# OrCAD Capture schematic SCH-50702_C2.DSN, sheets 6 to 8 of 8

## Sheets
6 06. MCU Link: size C
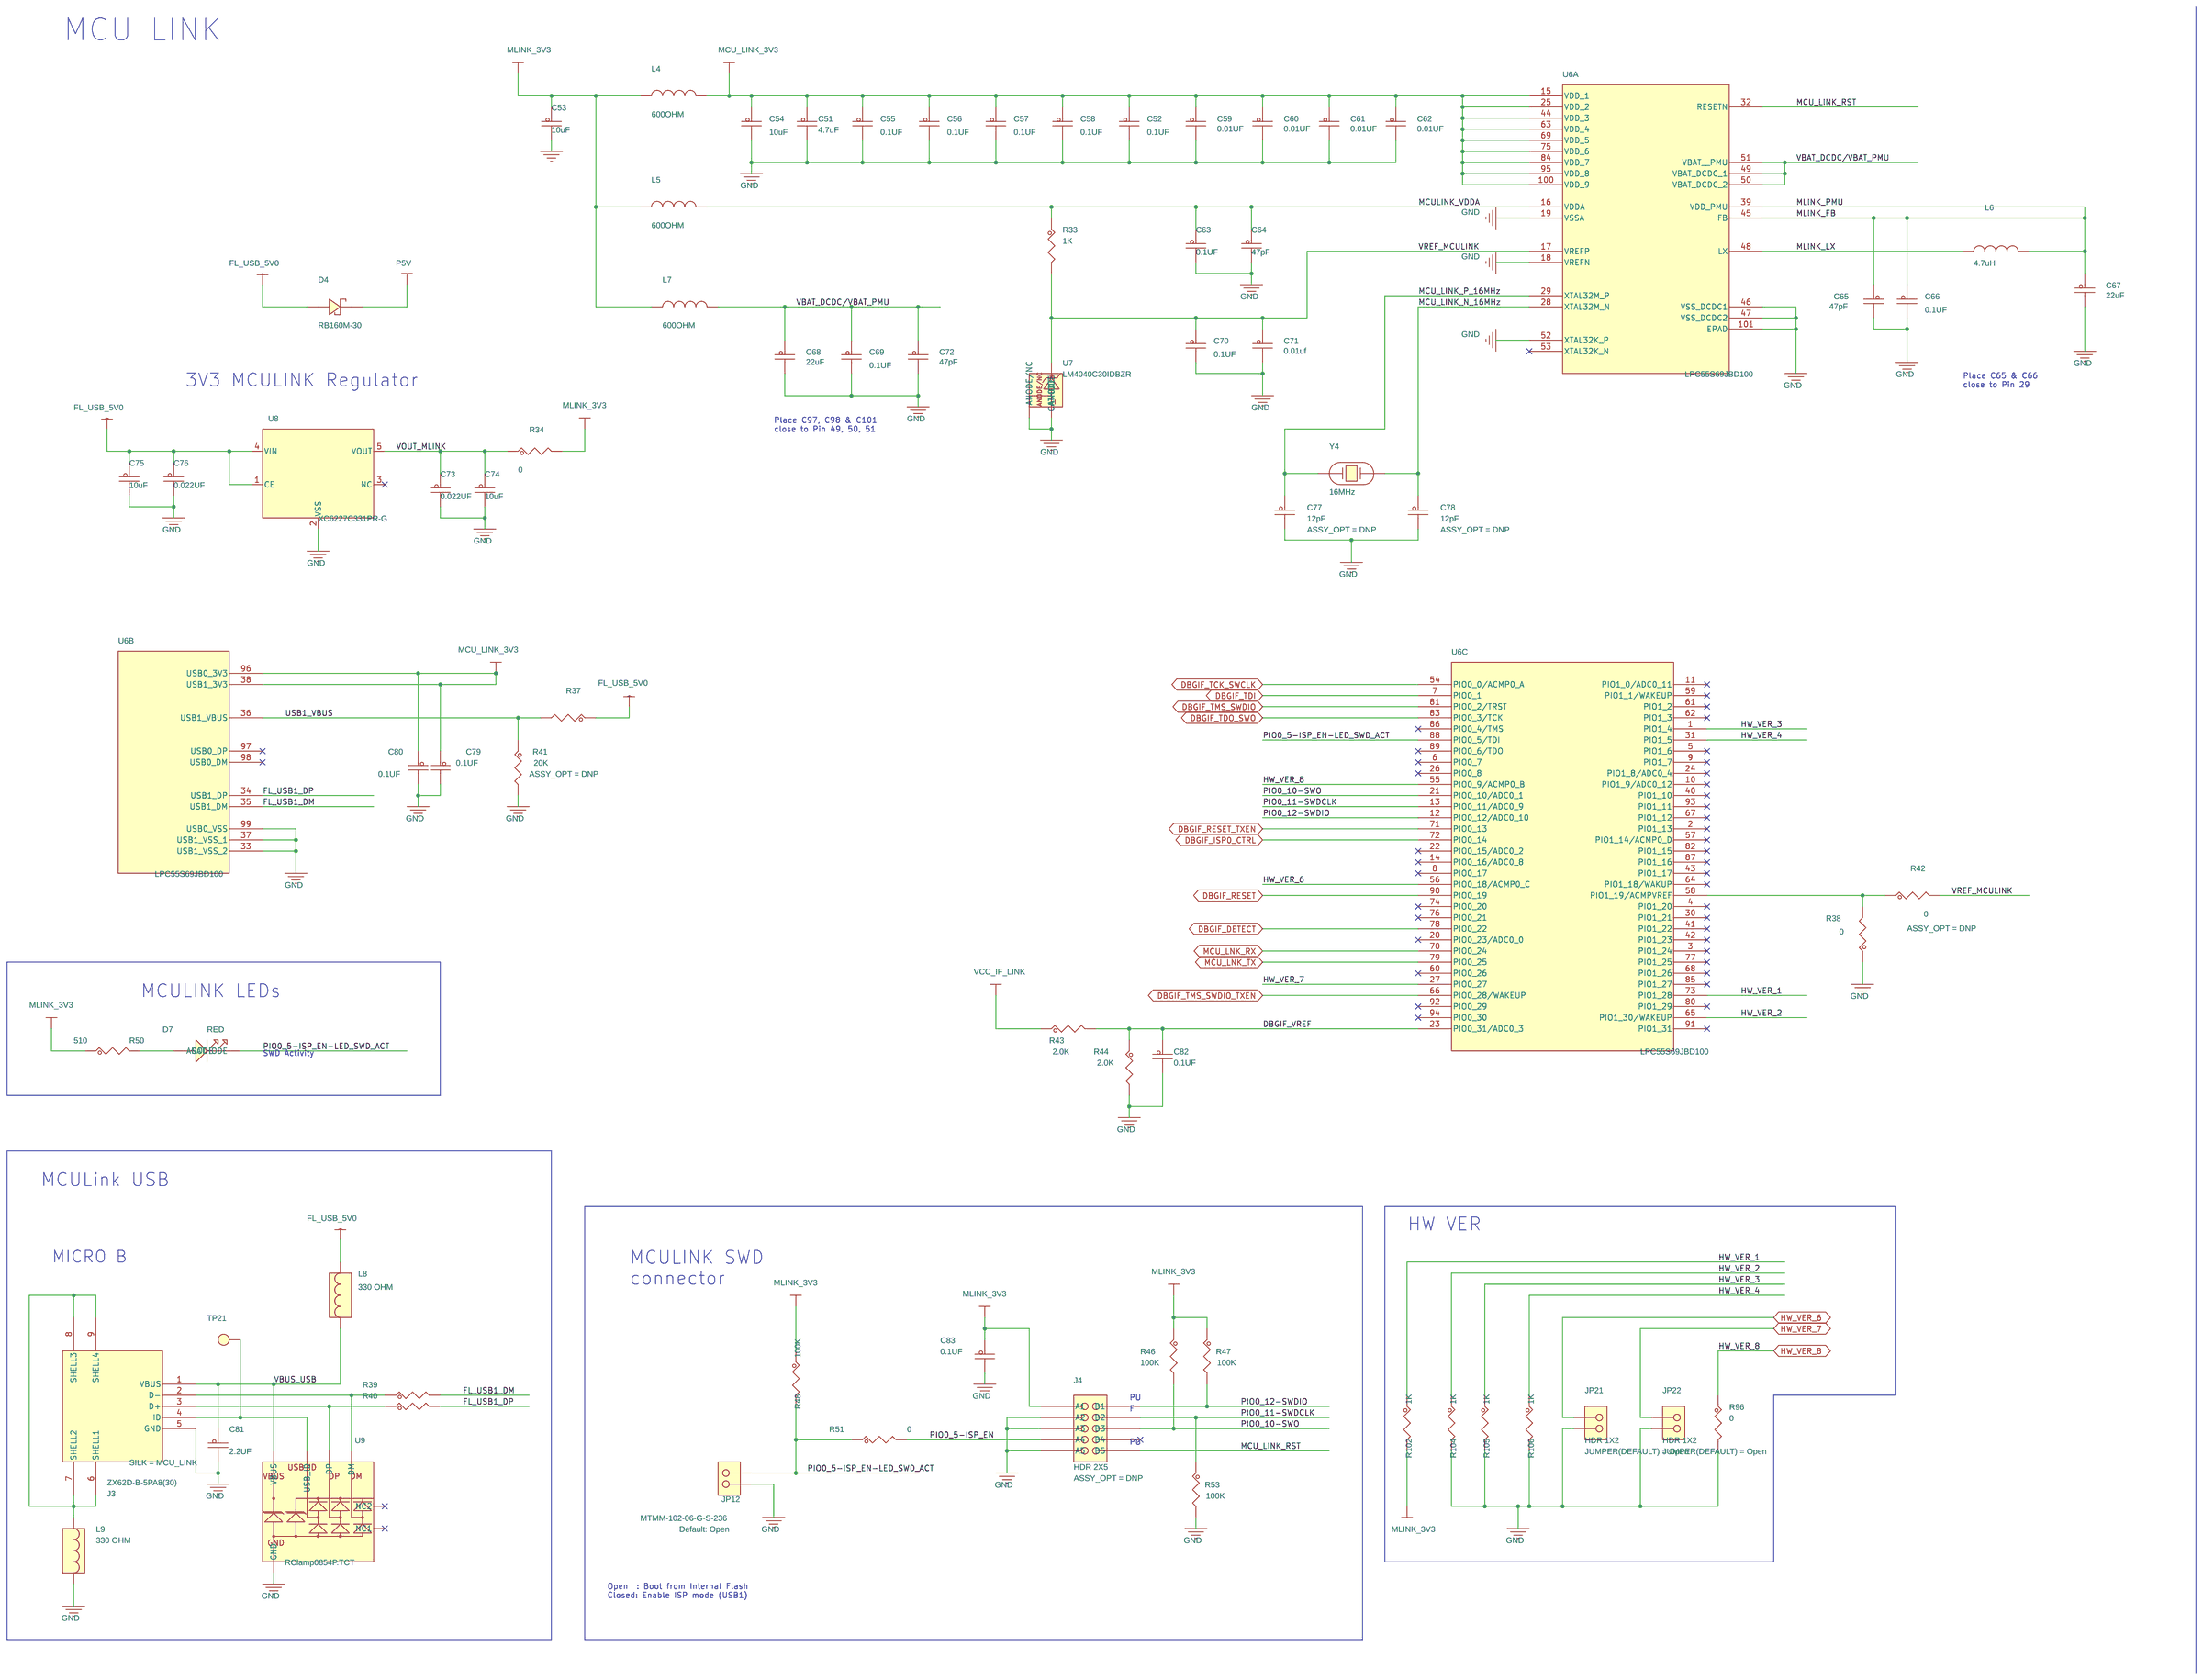
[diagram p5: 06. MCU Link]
7 07. MCU Link SWD: size C
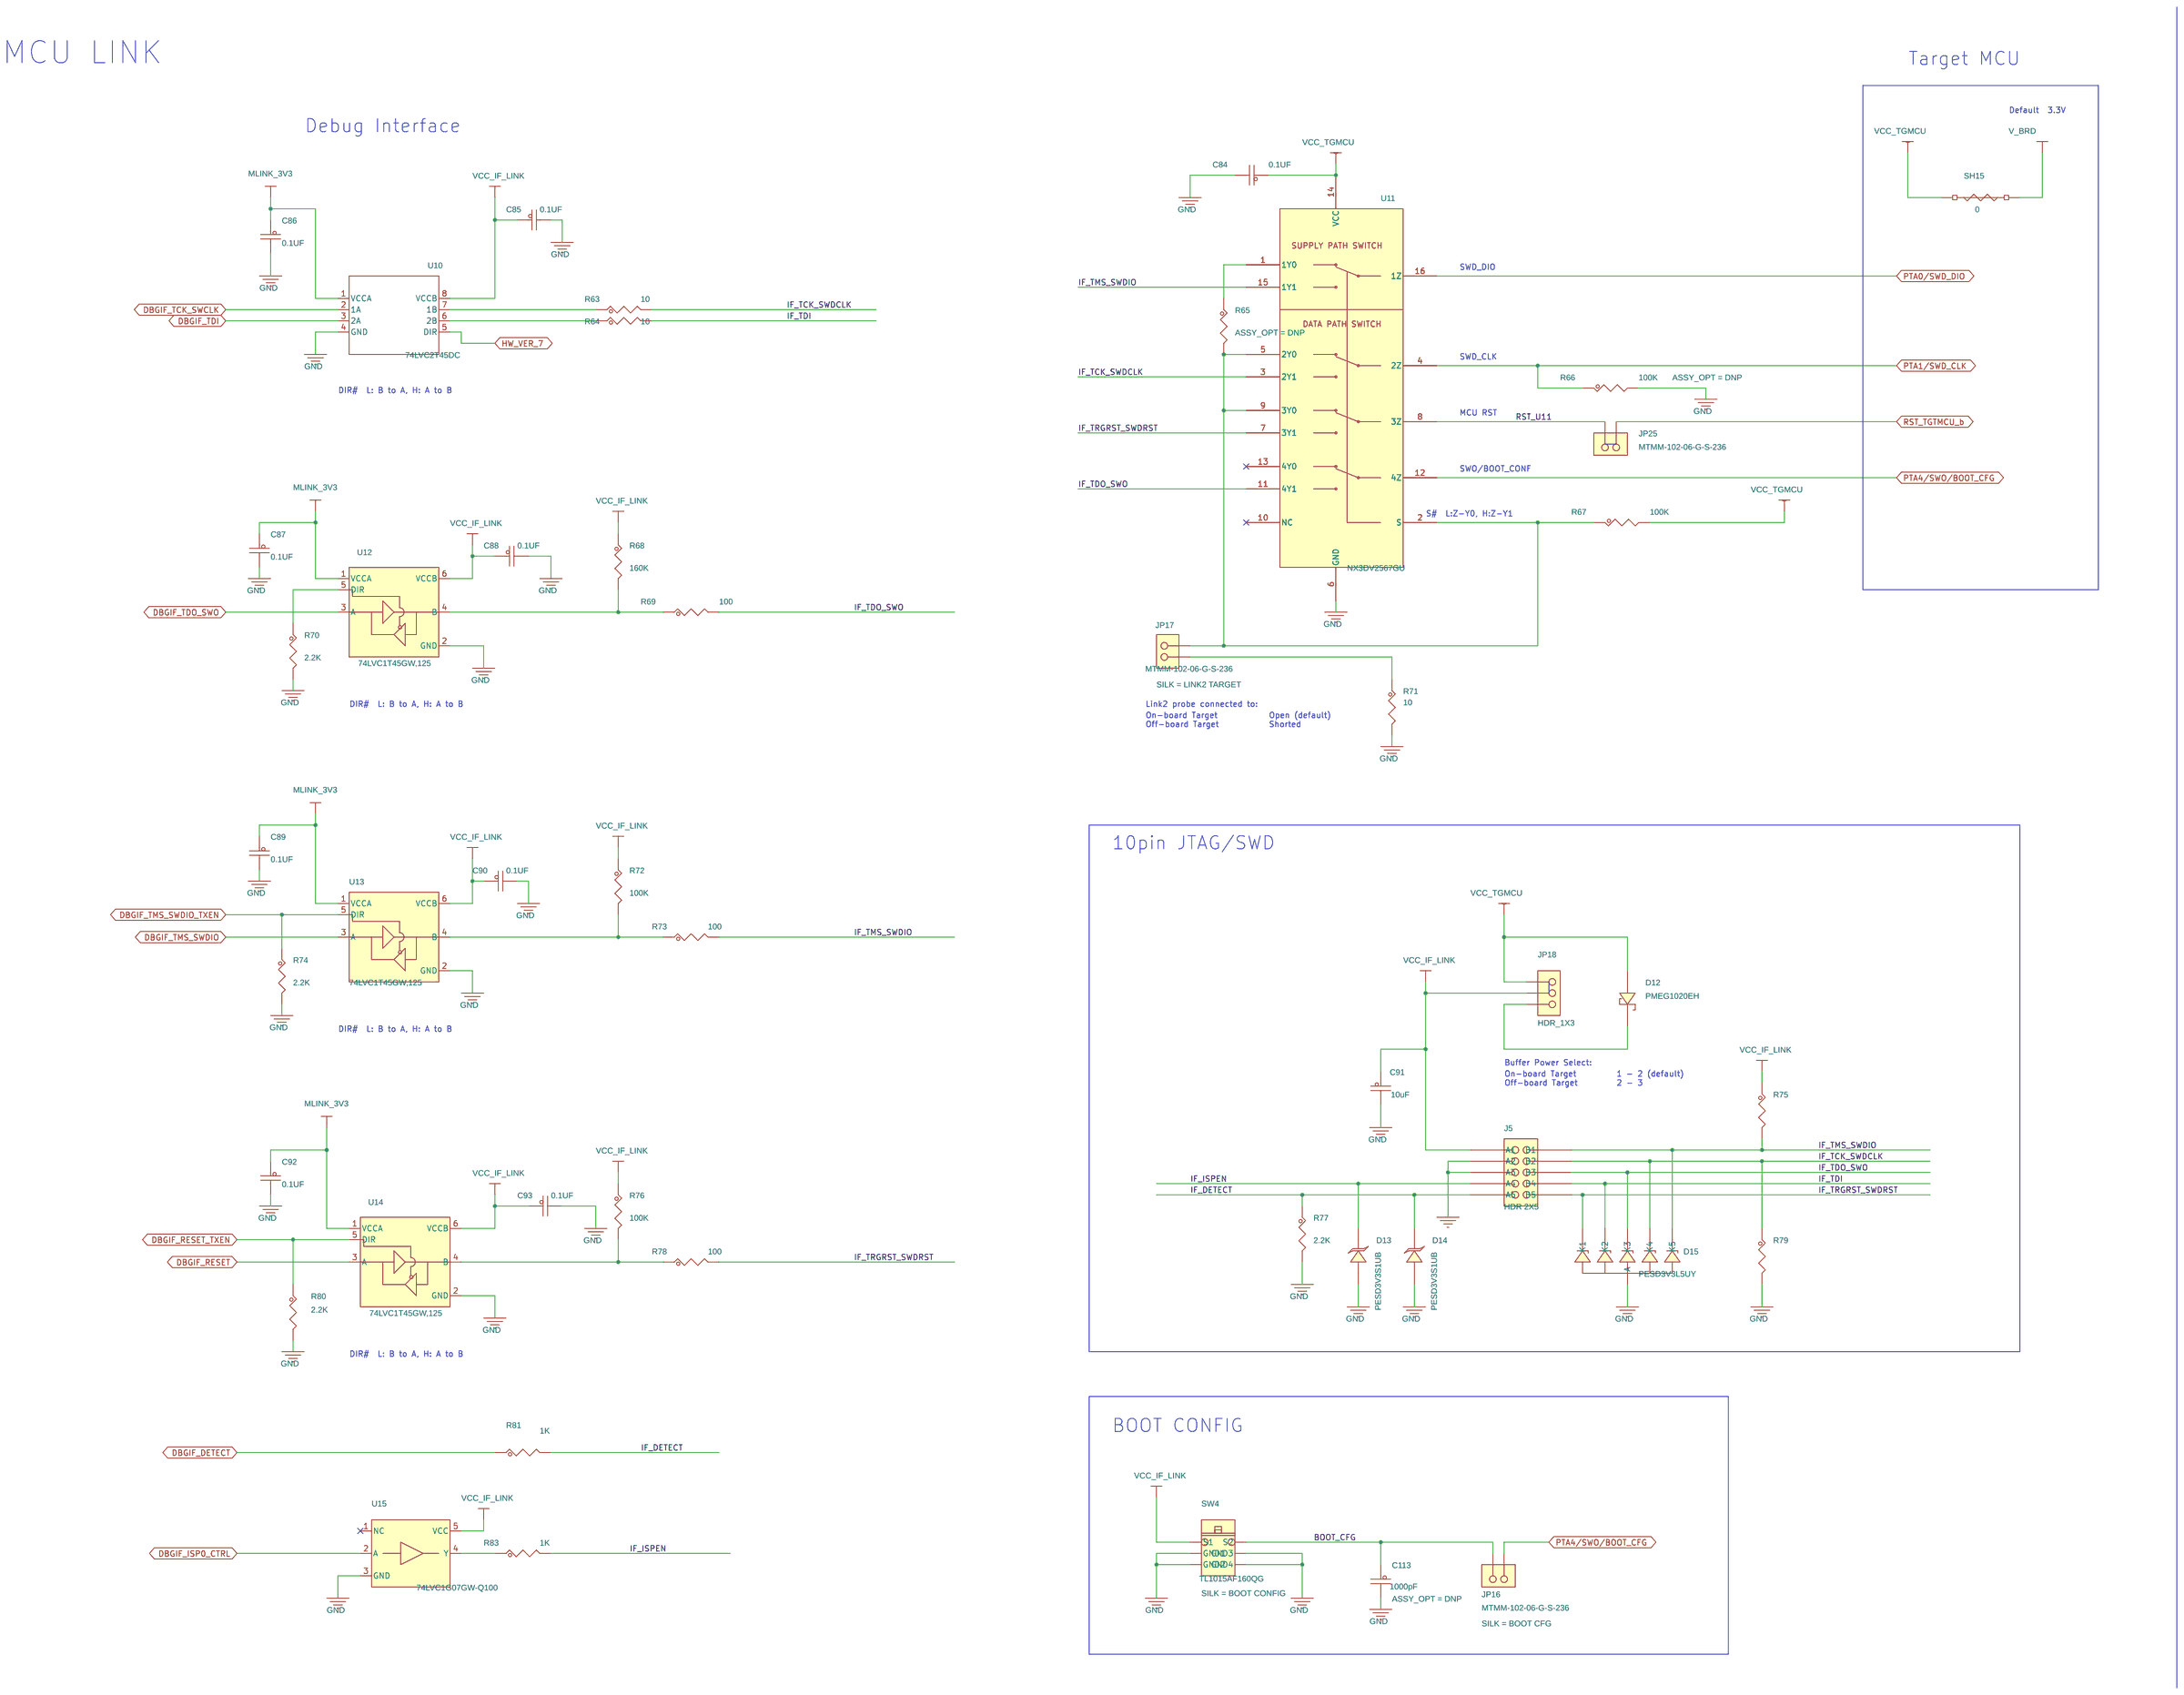
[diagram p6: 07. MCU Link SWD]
8 08. MCU Link IO: size C
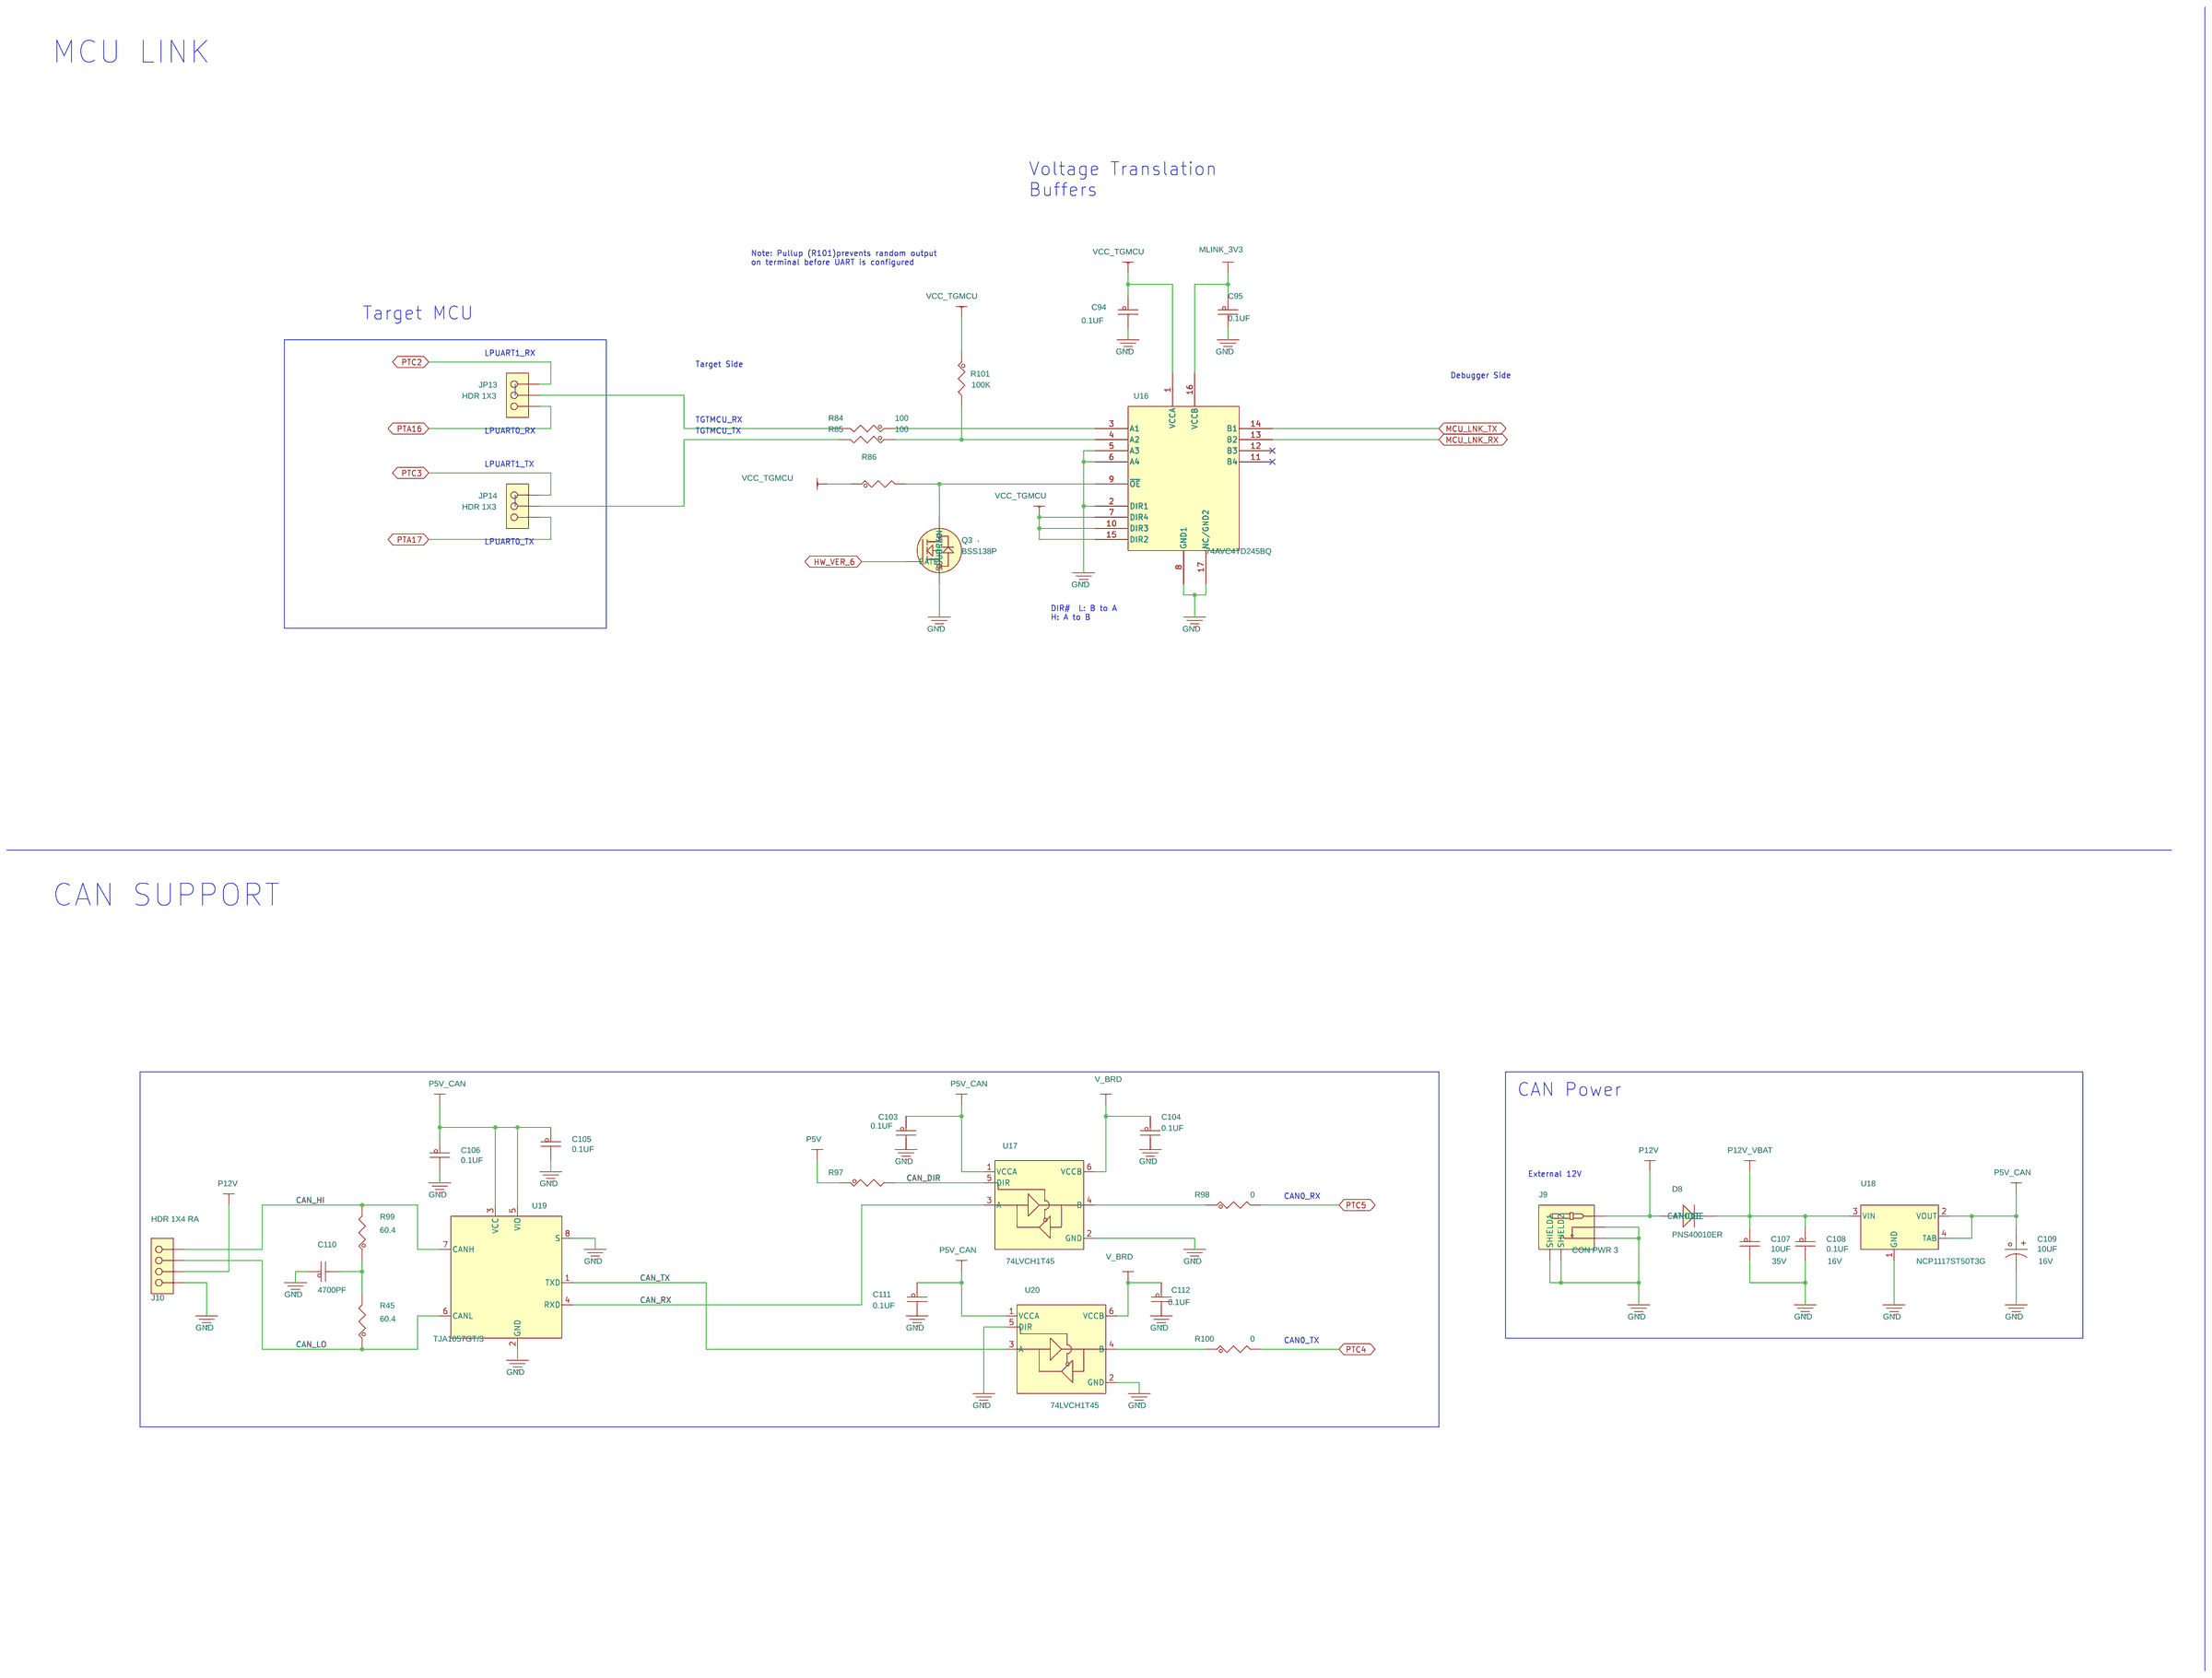
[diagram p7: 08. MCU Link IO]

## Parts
sheet 06. MCU Link
C51  4.7uF  [CC0603_OV]
C52  0.1UF  [CC0402_25]
C53  10uF  [CC0805_OV]
C54  10uF  [CC0805_OV]
C55  0.1UF  [CC0402_25]
C56  0.1UF  [CC0402_25]
C57  0.1UF  [CC0402_25]
C58  0.1UF  [CC0402_25]
C59  0.01UF  [CC0402_25]
C60  0.01UF  [CC0402_25]
C61  0.01UF  [CC0402_25]
C62  0.01UF  [CC0402_25]
C63  0.1UF  [CC0402_25]
C64  47pF  [CC0603_OV]
C65  47pF  [CC0603_OV]
C66  0.1UF  [CC0402_25]
C67  22uF  [CC0603_OV]
C68  22uF  [CC0603_OV]
C69  0.1UF  [CC0402_25]
C70  0.1UF  [CC0402_25]
C71  0.01uf  [CC0603_OV]
C72  47pF  [CC0603_OV]
C73  0.022UF  [CC0603_OV]
C74  10uF  [CC0805_OV]
C75  10uF  [CC0805_OV]
C76  0.022UF  [CC0603_OV]
C77  12pF  [CC0402_25]
C78  12pF  [CC0402_25]
C79  0.1UF  [CC0402_25]
C80  0.1UF  [CC0402_25]
C81  2.2UF  [CC0402_25]
C82  0.1UF  [CC0402_25]
C83  0.1UF  [CC0402_25]
D4  RB160M-30  [pmdu_sod123]
D7  RED  [LED_0603]
J3  ZX62D-B-5PA8(30)  [con9_microB_usb_shell_th]
J4  HDR 2X5  [hdr205_50_th]
JP12  MTMM-102-06-G-S-236  [hdr102_tmm]
JP21  HDR 1X2  [hdr102_338h]
JP22  HDR 1X2  [hdr102_338h]
L4  600OHM  [ind_1p8x1mm_sm]
L5  600OHM  [ind_1p8x1mm_sm]
L6  4.7uH  [ind_5p2x5p2]
L7  600OHM  [ind_1p8x1mm_sm]
L8  330 OHM  [ind_1608]
L9  330 OHM  [ind_1608]
R33  1K  [RC0402_25]
R34  0  [RC0603_OV]
R37  10K  [RC0603_OV]
R38  0  [RC0603_OV]
R39  0  [RC0402_25]
R40  0  [RC0402_25]
R41  20K  [RC0402_25]
R42  0  [RC0603_OV]
R43  2.0K  [RC0603_OV]
R44  2.0K  [RC0603_OV]
R46  100K  [RC0402_25]
R47  100K  [RC0402_25]
R48  100K  [RC0402_25]
R50  510  [RC0402_25]
R51  0  [RC0603_OV]
R53  100K  [RC0402_25]
R96  0  [RC0603_OV]
R102  1K  [RC0402_25]
R104  1K  [RC0402_25]
R105  1K  [RC0402_25]
R106  1K  [RC0402_25]
TP21  TP_35MIL  [testpoint_35mil]
U6  LPC55S69JBD100  [hlqfp100_0p5_14x14]  (sections A,B,C)
U7  LM4040C30IDBZR  [SOT23-3]
U8  XC6227C331PR-G  [SOT89-5]
U9  RClamp0854P.TCT  [slp1616p6]
Y4  16MHz  [xtal2_3p3x2p6]
sheet 07. MCU Link SWD
C84  0.1UF  [CC0402_25]
C85  0.1UF  [CC0402_25]
C86  0.1UF  [CC0402_25]
C87  0.1UF  [CC0402_25]
C88  0.1UF  [CC0402_25]
C89  0.1UF  [CC0402_25]
C90  0.1UF  [CC0402_25]
C91  10uF  [cc0402_tol0p2]
C92  0.1UF  [CC0402_25]
C93  0.1UF  [CC0402_25]
C113  1000pF  [CC0402_25]
D12  PMEG1020EH  [SOD123LF]
D13  PESD3V3S1UB  [sod523]
D14  PESD3V3S1UB  [sod523]
D15  PESD3V3L5UY  [sot-363_0p65_smt]
J5  HDR 2X5  [hdr205_50_th]
JP16  MTMM-102-06-G-S-236  [hdr102_tmm]
JP17  MTMM-102-06-G-S-236  [hdr102_tmm]
JP18  HDR_1X3  [hdr103_78mil]
JP25  MTMM-102-06-G-S-236  [hdr102_tmm]
R63  10  [RC0402_25]
R64  10  [RC0402_25]
R65  0  [RC0402_25]
R66  100K  [RC0402_25]
R67  100K  [RC0402_25]
R68  160K  [RC0402_25]
R69  100  [RC0402_25]
R70  2.2K  [RC0402_25]
R71  10  [RC0402_25]
R72  100K  [RC0402_25]
R73  100  [RC0402_25]
R74  2.2K  [RC0402_25]
R75  10K  [RC0402_25]
R76  100K  [RC0402_25]
R77  2.2K  [RC0402_25]
R78  100  [RC0402_25]
R79  10K  [RC0402_25]
R80  2.2K  [RC0402_25]
R81  1K  [RC0402_25]
R83  1K  [RC0402_25]
SH15  0  [SH0402]
SW4  TL1015AF160QG  [sw2_spst_4x3_sm]
U10  74LVC2T45DC  [SSOP8_DCU]
U11  NX3DV2567GU  [pqfn16_0p4_2p65x1p85]
U12  74LVC1T45GW,125  [SOT-363_0P65_SMT]
U13  74LVC1T45GW,125  [SOT-363_0P65_SMT]
U14  74LVC1T45GW,125  [SOT-363_0P65_SMT]
U15  74LVC1G07GW-Q100  [sc70-5]
sheet 08. MCU Link IO
C94  0.1UF  [CC0402_25]
C95  0.1UF  [CC0402_25]
C103  0.1UF  [CC0402_25]
C104  0.1UF  [CC0402_25]
C105  0.1UF  [CC0402_25]
C106  0.1UF  [CC0402_25]
C107  10UF  [CC0603_OV]
C108  0.1UF  [CC0402_25]
C109  10UF  [CC3216]
C110  4700PF  [CC0603_OV]
C111  0.1UF  [CC0402_25]
C112  0.1UF  [CC0402_25]
D8  PNS40010ER  [sod123w]
J9  CON PWR 3  [con3_pwr_jack_th_pj051a]
J10  HDR 1X4 RA  [con_hdr_4m_100_th_ra]
JP13  HDR 1X3  [CONN_HDR_3X1]
JP14  HDR 1X3  [CONN_HDR_3X1]
Q3  BSS138P  [sot23_a]
R45  60.4  [RC0805_OV]
R84  100  [RC0402_25]
R85  100  [RC0402_25]
R86  10K  [RC0402_25]
R97  4.7K  [RC0402_25]
R98  0  [RC0402_25]
R99  60.4  [RC0805_OV]
R100  0  [RC0402_25]
R101  100K  [RC0402_25]
U16  74AVC4TD245BQ  [dhvqfn16_0p5_3p6x2p6]
U17  74LVCH1T45  [udfn6_1x1p5mm]
U18  NCP1117ST50T3G  [sot223]
U19  TJA1057GT/3  [SO8_1P27_4X5]
U20  74LVCH1T45  [udfn6_1x1p5mm]

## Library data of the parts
C51 = CAP_NP: CAP CER 4.7uF 25V 10% X6S AEC-Q200 0603; AGILE_PN: 150-79698; CAD_APPROVED: Yes; FPLIST: CC0603_OV,CC0603; HEIGHT: 1MM; MFG_NAME01: MURATA; MFG_PN01: GRT188C81E475KE13; Package Size: 0603; ROHS: Yes; Rated Voltage: 25V; Temp Range: -55C to +105C; Tolerance: 10%; VOLTAGE: 25V
C52 C55-C58 C63 C66 C69 C70 C79 C80 C82 C103-C106 C108 C111 C112 = CAP_NP: CAP CER 0.1UF 16V 10% X7R 0402; 3D_Mechanical_Footprint_File: http://fcl.am.freescale.net/ALLEGRO/step/cc0402_25.STEP; AGILE_PN: 150-75182; CAD_APPROVED: Yes; FPLIST: CC0402_25,CC0402_HD,0402_CC,CAPC0402_L; HEIGHT: 0.635MM; MFG_NAME01: Samsung Electro-Mechanics; MFG_PN01: CL05B104KO5NNNC; ROHS: Yes; Rated Voltage: 16V; Temp Range: -55C to +125C; Tolerance: 10%; VOLTAGE: 16V
C53 C54 C74 C75 = CAP_NP: CAP CER 10uF 16V 20% X7S AEC-Q200 0805; AGILE_PN: 150-79516; CAD_APPROVED: Yes; FPLIST: CC0805_OV,CC0805,0805_CC; HEIGHT: 1.45MM; MFG_NAME01: TDK; MFG_PN01: CGA4J1X7S1C106M125AC; ROHS: Yes; Rated Voltage: 16V; Temp Range: -55C to +125C; Tolerance: 20%; VOLTAGE: 16V
C59-C62 = CAP_NP: CAP CER 0.01UF 25V 10% X8R 0402; AGILE_PN: 150-77996; CAD_APPROVED: Yes; FPLIST: CC0402_25,CC0402_HD,0402_CC; HEIGHT: 0.55MM; MFG_NAME01: TDK; MFG_PN01: C1005X8R1E103K050BA; ROHS: Yes; Rated Voltage: 25V; Temp Range: -55C to +150C; Tolerance: 10%; VOLTAGE: 25V
C64 C65 C72 = CAP_NP: CAP CER 47pF 50V 5% C0G AEC-Q200 0603; AGILE_PN: 150-79357; CAD_APPROVED: Yes; FPLIST: CC0603_OV,CC0603,0603_CC; HEIGHT: 0.9MM; MFG_NAME01: TDK; MFG_PN01: CGA3E2C0G1H470J080AA; Package Size: 0603; Package Type: Reel; ROHS: Yes; Rated Voltage: 50V; Temp Range: -55C to +125C; Tolerance: 5%; VOLTAGE: 50V
C67 C68 = CAP_NP: CAP CER 22uF 10V 20% X5R 0603; AGILE_PN: 150-79530; CAD_APPROVED: Yes; FPLIST: CC0603_OV,CC0603; HEIGHT: 1MM; MFG_NAME01: SAMSUNG; MFG_PN01: CL10A226MP7LUNC; Package Size: 0603; ROHS: Yes; Rated Voltage: 10V; Temp Range: -55C to +85C; Tolerance: 20%; VOLTAGE: 10V
C71 = CAP_NP: CAP CER 0.01uF 50V 10% X7R AEC-Q200 0603; AGILE_PN: 150-79361; CAD_APPROVED: Yes; FPLIST: CC0603_OV,CC0603,0603_CC; HEIGHT: 0.9MM; MFG_NAME01: TDK; MFG_PN01: CGA3E2X7R1H103K080AA; Package Size: 0603; Package Type: 7; ROHS: Yes; Rated Voltage: 50V; Temp Range: -55C to +125C; Tolerance: 10%; VOLTAGE: 50V
C73 C76 = CAP_NP: CAP CER 0.022UF 50V 20% X7R 0603; AGILE_PN: 150-30153; CAD_APPROVED: Yes; FPLIST: CC0603_OV,CC0603,0603_CC; HEIGHT: 0.86MM; MFG_NAME01: AVX; MFG_PN01: 06035C223MAT2A; Package Size: 0603; ROHS: Yes; Rated Voltage: 50V; Temp Range: -55C to +125C; Tolerance: 20%; VOLTAGE: 50V
C77 C78 = CAP_NP: CAP CER 12pF 50V 5% C0G AEC-Q200 0402; AGILE_PN: 150-80457; ASSY_OPT: DNP; CAD_APPROVED: Yes; FPLIST: CC0402_25,CC0402_HD,0402_CC,capc0402_l; HEIGHT: 0.55MM; MFG_NAME01: MURATA; MFG_PN01: GCM1555C1H120JA16D; Package Size: 0402; ROHS: Yes; Rated Voltage: 50V; Temp Range: -55C to +125C; Tolerance: 5%; VOLTAGE: 50V
C81 = CAP_NP: CAP CER 2.2UF 10V 10% X5R 0402; AGILE_PN: 150-79475; CAD_APPROVED: Yes; FPLIST: CC0402_25,CC0402_HD,0402_CC; HEIGHT: 0.56MM; MFG_NAME01: AVX; MFG_PN01: 0402ZD225KAT2A; Package Size: 0402; ROHS: Yes; Rated Voltage: 10V; Temp Range: -55C to +85C; Tolerance: 10%; VOLTAGE: 10V
C83 = CAP_NP: CAP CER 0.1UF 16V 10% X7R 0402; 3D_Mechanical_Footprint_File: http://fcl.am.freescale.net/ALLEGRO/step/cc0402_25.STEP; AGILE_PN: 150-75182; CAD_APPROVED: Yes; FPLIST: CC0402_25,CC0402_HD,0402_CC,CAPC0402_L; HEIGHT: 0.635MM; MFG_NAME01: Samsung Electro-Mechanics; MFG_PN01: CL05B104KO5NNNC; ROHS: Yes; Rated Voltage: 16V; Temp Range: -55C to +125C; Temp_Range: -55°C to +125°C; Tolerance: 10%; VOLTAGE: 16V
D4 = DIODE_SCHTKY: DIODE SCH 1A 30V SOD123; 3D_Mechanical_Footprint_File: http://fcl.am.freescale.net/ALLEGRO/step/pmdu_sod123.STEP; AGILE_PN: 480-79681; CAD_APPROVED: Yes; HEIGHT: 0.9MM; MFG_NAME01: ROHM; MFG_PN01: RB160M-30TR; ROHS: Yes
D7 = LED: LED RED SGL 20MA SMT; AGILE_PN: 370-76568; CAD_APPROVED: Yes; HEIGHT: 0.67MM; MFG_NAME01: OSRAM; MFG_PN01: LS L29K-H1J2-1; ROHS: Yes; Rated Voltage: 1.8V; VOLTAGE: 1.8V
J3 = MICRO_USB_CONN_9PIN: CON 5 MICRO USB_TYPE_B 2.0 RA SMT SKT TH 0.65MM SP 104H AU; AGILE_PN: 210-82071; CAD_APPROVED: Yes; HEIGHT: 2.65MM; MFG_NAME01: HIROSE; Package Type: TH; ROHS: Yes; SILK: MCU_LINK; Temp Range: -35 to 85&#8451;; Temp_Range: -35 to 85&#8451;; VOLTAGE: 100V
J4 = CONN_HDR_5X2: HDR 2X5 TH 50MIL CTR 172H AU 91L; AGILE_PN: 210-81466; ASSY_OPT: DNP; CAD_APPROVED: Yes; HEIGHT: 4.38MM; MFG_NAME01: ANYTRONIC CORPORATION LIMITED; MFG_PN01: 0922S0205011N9T-31RF; ROHS: Yes; Temp Range: -55DegC to +105DegC; Temp_Range: -55DegC to +105DegC
JP12 = CONN_HDR_2X1: HDR 1X2 TH 2MM SP 300H AU 102L; AGILE_PN: 210-80456; CAD_APPROVED: Yes; HEIGHT: 7.62MM; Jumper: Default: Open; MFG_NAME01: SAMTEC; ROHS: Yes
JP21 JP22 = CONN_HDR_2X1: HDR 1X2 TH 100MIL SP 338H SN 100L; 3D_Mechanical_Footprint_File: http://fcl.am.freescale.net/ALLEGRO/step/hdr102_338h.STEP; AGILE_PN: 210-80102; CAD_APPROVED: Yes; HEIGHT: 8.58MM; JUMPER(DEFAULT): Open; MFG_NAME01: SAMTEC; MFG_PN01: TSW-102-07-T-S; Package Size: 5.08 x 2.54 mm; ROHS: Yes; Temp Range: -55°C to +125°C
L4 L5 L7 = INDUCTOR: IND FER BEAD 600OHM@100MHz 1A 25% 0603; 3D_Mechanical_Footprint_File: http://fcl.am.freescale.net/ALLEGRO/step/ind_1p8x1mm_sm.step; AGILE_PN: 180-78469; CAD_APPROVED: Yes; HEIGHT: 1MM; MFG_NAME01: WURTH ELEKTRONIK EISOS GMBH & CO. KG (ELECTRONIC & ELECTROMEHANICAL COMP); MFG_PN01: 742792651; ROHS: Yes
L6 = INDUCTOR: IND WW PWR 4.7UH@40MHZ 3A 30% SMT; 3D_Mechanical_Footprint_File: http://fcl.am.freescale.net/ALLEGRO/step/ind_5p2x5p2.STEP; AGILE_PN: 180-78209; CAD_APPROVED: Yes; HEIGHT: 2.2MM; MFG_NAME01: MURATA; MFG_PN01: LQH5BPN4R7NT0; ROHS: Yes
L8 L9 = BEAD: IND FER BEAD 330OHM@100MHZ 1.7A 0603; AGILE_PN: 180-78156; CAD_APPROVED: Yes; FPLIST: ind_1608,0603_CC; HEIGHT: 0.95MM; MFG_NAME01: TDK; MFG_PN01: MPZ1608S331A; PART_TYPE: FERRITE\BEAD; ROHS: Yes; Tolerance: 25%
R33 R81 R83 R102 R104-R106 = RES: RES MF 1K 1/16W 0.5% 0402; AGILE_PN: 470-80057; CAD_APPROVED: Yes; FPLIST: RC0402_25,RC0402_HD,0402_CC; HEIGHT: 0.4MM; MFG_NAME01: PANASONIC; MFG_PN01: ERA2AED102X; ROHS: Yes; Tolerance: 0.5%
R34 R38 R51 R96 = RES: RES MF ZERO OHM 1/10W -- 0603; AGILE_PN: 470-80866; CAD_APPROVED: Yes; FPLIST: RC0603_OV,RC0603,R603-X2,0603_CC; HEIGHT: 0.6MM; MFG_NAME01: YAGEO AMERICA; MFG_PN01: RC0603FR-070RL; ROHS: Yes; Temp Range: –55 °C to +155 °C
R37 = RES: RES MF 10K 1/10W 5% 0603; AGILE_PN: 470-75410; CAD_APPROVED: Yes; FPLIST: RC0603_OV,RC0603,0603_CC; HEIGHT: 0.55MM; MFG_NAME01: BOURNS; MFG_PN01: CR0603-JW-103ELF; ROHS: Yes; Temp Range: –55 °C to +155 °C; Tolerance: 5%
R39 R40 = RES: RES MF ZERO OHM 1/16W 5% 0402; AGILE_PN: 470-75394; CAD_APPROVED: Yes; FPLIST: RC0402_25,RC0402_HD,RC0402_X2,0402_CC; HEIGHT: 0.45 MM; MFG_NAME01: BOURNS; MFG_PN01: CR0402-J/-000GLF; ROHS: Yes; Tolerance: 5%; VOLTAGE: 1/16W
R41 = RES: RES MF 20K 1/10W 0.1% AEC-Q200 0402; AGILE_PN: 470-82089; ASSY_OPT: DNP; CAD_APPROVED: Yes; FPLIST: RC0402_25,RC0402_HD,0402_CC; HEIGHT: 0.4MM; MFG_NAME01: VISHAY INTERTECHNOLOGY; MFG_PN01: MCS0402MD2002BE100; ROHS: Yes; Temp Range: -55°C ~ 125°C; Tolerance: 0.1%; VOLTAGE: 50V
R42 = RES: RES MF ZERO OHM 1/10W -- 0603; AGILE_PN: 470-80866; ASSY_OPT: DNP; CAD_APPROVED: Yes; FPLIST: RC0603_OV,RC0603,R603-X2,0603_CC; HEIGHT: 0.6MM; MFG_NAME01: YAGEO AMERICA; MFG_PN01: RC0603FR-070RL; ROHS: Yes; Temp Range: –55 °C to +155 °C
R43 R44 = RES: RES MF 2.0K 1/10W 5% 0603; AGILE_PN: 470-75408; CAD_APPROVED: Yes; FPLIST: RC0603_OV,RC0603,0603_CC; HEIGHT: 0.55MM; MFG_NAME01: BOURNS; MFG_PN01: CR0603-JW-202ELF; ROHS: Yes; Tolerance: 5%; VOLTAGE: 1/10W
R46-R48 R53 R67 R72 R76 R101 = RES: RES MF 100K 1/16W 1% 0402; AGILE_PN: 470-76240; CAD_APPROVED: Yes; FPLIST: RC0402_25,RC0402_HD,0402_CC; HEIGHT: 0.4MM; MFG_NAME01: BOURNS; MFG_PN01: CR0402-FX-1003GLF; ROHS: Yes; Tolerance: 1%
R50 = RES: RES 510 OHMS 1/16W 5% RC0402 ROHS; AGILE_PN: 470-76237; CAD_APPROVED: Yes; FPLIST: RC0402_25,RC0402_HD,0402_CC; HEIGHT: 0.4 MM; MFG_NAME01: YAGEO AMERICA; MFG_PN01: RC0402JR-07510RL; ROHS: Yes; Temp_Range: -55C to +155C
TP21 = T_POINT_R: TEST POINT PAD .035 SMT, no part to order; AGILE_PN: 510-75618; CAD_APPROVED: Yes; HEIGHT: 0.1MM; ROHS: Yes
U6 = LPC55S69JB_HLQFP100: IC MCU 32BIT ARM FLASH 640KB SRAM 320KB 1.8-3.6V HLQFP100; 3D_Mechanical_Footprint_File: http://fcl.am.freescale.net/ALLEGRO/step/hlqfp100_0p5_14x14.step; AGILE_PN: 344-02385; CAD_APPROVED: Yes; HEIGHT: 1.6MM; MFG_NAME01: NXP SEMICONDUCTOR; ROHS: Yes; Temp Range: -40C to +105C; VOLTAGE: 1.8-3.6V
U7 = LM4040_SOT23: IC VOLT REF SHUNT 3V 0.5% SOT23-3; AGILE_PN: 315-80874; CAD_APPROVED: Yes; HEIGHT: 1.13MM; MFG_NAME01: TEXAS INSTRUMENTS; ROHS: Yes; VOLTAGE: 3V
U8 = XC6227C_5P: IC VREG LDO  3.3V 0.7A 1.7-6.0V SOT-89-5; AGILE_PN: 315-80827; CAD_APPROVED: Yes; HEIGHT: 1.6MM; MFG_NAME01: TOREX; ROHS: Yes; VOLTAGE: 1.7V ~ 6.0V
U9 = RCLAMP1654P_NEW: DIODE TVS ARRAY 3 5.5V SLP1616P6; 3D_Mechanical_Footprint_File: http://fcl.am.freescale.net/ALLEGRO/step/slp1616p6.step; AGILE_PN: 480-78843; CAD_APPROVED: Yes; HEIGHT: 0.65MM; MFG_NAME01: SEMTECH CORP; ROHS: Yes; Rated Voltage: 5.5V; VOLTAGE: 5.5V
Y4 = XTAL: XTAL 16MHZ 8PF AEC-Q200 SMT; 3D_Mechanical_Footprint_File: http://fcl.am.freescale.net/ALLEGRO/step/xtal2_3p3x2p6.STEP; AGILE_PN: 230-78366; CAD_APPROVED: Yes; Frequency Stability: 150ppm; Frequency Tolerance: 50ppm; HEIGHT: 0.037" (0.95mm); MFG_NAME01: Kyocera International Inc. Electronic Components; MFG_PN01: CX3225GA16000D0PTVCC; Package Size: 0.126" L x 0.098" W (3.20mm x 2.50mm); ROHS: Yes; Temp Range: -40 to 150 °C
C84-C90 C92-C95 = CAP_NP: CAP CER 0.1UF 16V 10% X7R 0402; 3D_Mechanical_Footprint_File: http://fcl.am.freescale.net/ALLEGRO/step/cc0402_25.STEP; AGILE_PN: 150-75182; CAD_APPROVED: Yes; FPLIST: CC0402_25,CC0402_HD,0402_CC; HEIGHT: 0.635MM; MFG_NAME01: Samsung Electro-Mechanics; MFG_PN01: CL05B104KO5NNNC; ROHS: Yes; Rated Voltage: 16V; Temp Range: -55C to +125C; Temp_Range: -55°C to +125°C; Tolerance: 10%; VOLTAGE: 16V
C91 = CAP_NP: CAP CER 10uF 10V 20% X5R 0402_WIDE; AGILE_PN: 150-79255; CAD_APPROVED: Yes; FPLIST: CC0402_25,CC0402_HD,0402_CC; HEIGHT: 0.7MM; MFG_NAME01: NIC COMPONENTS CORP; MFG_PN01: NMC0402X5R106M10TRPF; ROHS: Yes; Rated Voltage: 10V; Temp Range: -55C to +85C; Tolerance: 20%; VOLTAGE: 10V
C113 = CAP_NP: CAP CER 1000PF 50V 5% C0G 0402; AGILE_PN: 150-76334; ASSY_OPT: DNP; CAD_APPROVED: Yes; FPLIST: CC0402_25,CC0402_HD,0402_CC; HEIGHT: 0.55MM; MFG_NAME01: MURATA; MFG_PN01: GRM1555C1H102JA01D; Package Size: 0402; Package Type: 180mm Paper Tape; ROHS: Yes; Rated Voltage: 50V; Temp Range: -55C to +125C; Tolerance: 5%; VOLTAGE: 50V
D12 = DIODE_SCHTKY: DIODE SCH RECT 10V 2A SOD123F; AGILE_PN: 480-78720; CAD_APPROVED: Yes; HEIGHT: 1.2M; MFG_NAME01: NEXPERIA; MFG_PN01: PMEG1020EH,115; ROHS: Yes; Rated Voltage: 10V; VOLTAGE: 10V
D13 D14 = DIODE_TVS: DIODE TVS UNIDIR 3.3VWM 20VC SOD523; AGILE_PN: 480-79814; CAD_APPROVED: Yes; HEIGHT: 0.65MM; MFG_NAME01: NEXPERIA; MFG_PN01: PESD3V3S1UB,115; REQUESTED_COMPLETION_DATE: Not an expedite request; ROHS: Yes
D15 = DIODE_ARRAY_5CH: DIODE TVS UNIDIR 3.3VWM 12VC SOT363; AGILE_PN: 480-79841; CAD_APPROVED: Yes; HEIGHT: 1.1MM; MFG_NAME01: NEXPERIA; MFG_PN01: PESD3V3L5UY,115; REQUESTED_COMPLETION_DATE: Not an expedite request; ROHS: Yes; Temp Range: -65°C ~ 150°C; Temp_Range: -65°C ~ 150°C
J5 = CONN_HDR_5X2: HDR 2X5 TH 50MIL CTR 172H AU 91L; AGILE_PN: 210-81466; CAD_APPROVED: Yes; HEIGHT: 4.38MM; Jumper (Default): OPEN; MFG_NAME01: ANYTRONIC CORPORATION LIMITED; MFG_PN01: 0922S0205011N9T-31RF; ROHS: Yes; Temp Range: -55DegC to +105DegC; Temp_Range: -55DegC to +105DegC
JP16 = CONN_HDR_2X1: HDR 1X2 TH 2MM SP 300H AU 102L; AGILE_PN: 210-80456; CAD_APPROVED: Yes; HEIGHT: 7.62MM; Jumper (Default): 1-2; MFG_NAME01: SAMTEC; ROHS: Yes; SILK: BOOT CFG; Temp_Range: -55°C to +105°C
JP17 = CONN_HDR_2X1: HDR 1X2 TH 2MM SP 300H AU 102L; AGILE_PN: 210-80456; CAD_APPROVED: Yes; HEIGHT: 7.62MM; Jumper (Default): OPEN; MFG_NAME01: SAMTEC; ROHS: Yes; SILK: LINK2 TARGET; Temp_Range: -55°C to +105°C
JP18 = CONN_HDR_3X1: HDR 1X3 TH 2MM SP 295H AU 102L; AGILE_PN: 210-80201; CAD_APPROVED: Yes; HEIGHT: 7.5 MM; MFG_NAME01: SAMTEC; MFG_PN01: MTMM-103-06-G-S-236; ROHS: Yes; Temp_Range: -55°C to +125°C
JP25 = CONN_HDR_2X1: HDR 1X2 TH 2MM SP 300H AU 102L; AGILE_PN: 210-80456; CAD_APPROVED: Yes; HEIGHT: 7.62MM; Jumper (Default): 1-2; MFG_NAME01: SAMTEC; ROHS: Yes; Temp_Range: -55°C to +105°C
R63 R64 R71 = RES: RES MF 10 OHM 1/16W 1% AEC-Q200 0402; AGILE_PN: 470-80978; CAD_APPROVED: Yes; FPLIST: RC0402_25,RC0402_HD,0402_CC; HEIGHT: 0.4MM; MFG_NAME01: KOA SPEER; MFG_PN01: RK73H1ETTP10R0F; ROHS: Yes; Temp Range: –55 °C to +155 °C; Tolerance: 1%
R65 = RES: RES MF ZERO OHM 1/16W 5% 0402; AGILE_PN: 470-75394; ASSY_OPT: DNP; CAD_APPROVED: Yes; FPLIST: RC0402_25,RC0402_HD,RC0402_X2,0402_CC; HEIGHT: 0.45 MM; MFG_NAME01: BOURNS; MFG_PN01: CR0402-J/-000GLF; ROHS: Yes; Tolerance: 5%; VOLTAGE: 1/16W
R66 = RES: RES MF 100K 1/16W 1% 0402; AGILE_PN: 470-76240; ASSY_OPT: DNP; CAD_APPROVED: Yes; FPLIST: RC0402_25,RC0402_HD,0402_CC; HEIGHT: 0.4MM; MFG_NAME01: BOURNS; MFG_PN01: CR0402-FX-1003GLF; ROHS: Yes; Tolerance: 1%
R68 = RES: RES MF 160K 1/16W 5% AEC-Q200 0402; AGILE_PN: 470-80970; CAD_APPROVED: Yes; HEIGHT: 0.4 MM; MFG_NAME01: KOA SPEER; MFG_PN01: RK73B1ETTP164J; ROHS: Yes; Tolerance: 5%
R69 R73 R78 R84 R85 = RES: RES MF 100 OHM 1/16W 5% 0402; AGILE_PN: 470-75591; CAD_APPROVED: Yes; FPLIST: RC0402_25,RC0402_HD,RC0402_X2,0402_CC; HEIGHT: 0.45mm; MFG_NAME01: BOURNS; MFG_PN01: CR0402-JW-101GLF; ROHS: Yes; Tolerance: 5%
R70 R74 R77 R80 = RES: RES MF 2.2K 1/16W 1% 0402; AGILE_PN: 470-78359; CAD_APPROVED: Yes; FPLIST: RC0402_25,RC0402_HD,0402_CC; HEIGHT: 0.4MM; MFG_NAME01: NIC COMPONENTS CORP; MFG_PN01: NRCL04F2201TRF; ROHS: Yes; Temp Range: -55C to +155C; Temp_Range: -55C to +155C; Tolerance: 1%
R75 R79 = RES: RES MF 10K 1/16W 1% 0402; AGILE_PN: 470-80452; CAD_APPROVED: Yes; FPLIST: RC0402_25,RC0402_HD,0402_CC,RC0402_X2; HEIGHT: 0.40 MM; MFG_NAME01: NIC COMPONENTS CORP; MFG_PN01: NRCL04F1002TRF; ROHS: Yes; Tolerance: 1%
SH15 = RES_SHORT-2: ZERO OHM CUT TRACE 0402 PADS; NO PART TO ORDER; AGILE_PN: 470-76449; CAD_APPROVED: Yes; FPLIST: SH0402,SH0402_CC; HEIGHT: 0.1 MM; ROHS: Yes; SHORTED (DEFAULT): CLOSED
SW4 = SW_SPNO_2P_GND6P: SW SPST PB 50MA 12V SMT; AGILE_PN: 510-77720; CAD_APPROVED: Yes; HEIGHT: 2.4MM; MFG_NAME01: E SWITCH; ROHS: Yes; SILK: BOOT CONFIG
U10 = 74LVC2T45DC_8P: IC TRANSLATING XCVR DUAL BIT/SUPPLY TS 1.2-5.5V VSSOP8; 3D_Mechanical_Footprint_File: http://fcl.am.freescale.net/ALLEGRO/step/ssop8_dcu.STEP; AGILE_PN: 312-81751; CAD_APPROVED: Yes; HEIGHT: 1MM; MFG_NAME01: NEXPERIA; ROHS: Yes; Temp Range: -40°C to +125°C; VOLTAGE: 1.2 -5.5V
U11 = NX3DV2567GU_XQFN_16P: IC LIN SW 4PDT 1.4-4.3V XQFN16; 3D_Mechanical_Footprint_File: http://fcl.am.freescale.net/ALLEGRO/step/pqfn16_0p4_2p65x1p85.STEP; AGILE_PN: 315-80822; CAD_APPROVED: Yes; HEIGHT: 0.5 MM; MFG_NAME01: NXP SEMICONDUCTOR; MFG_PN01: NX3DV2567GU,115; ROHS: Yes; VOLTAGE: 1.4-4.3V
U12-U14 = 74LVCH1T45_6P: IC XCVR XLATING DUAL 3-STATE 1.2- 5.5V TSSOP6; AGILE_PN: 312-81277; CAD_APPROVED: Yes; HEIGHT: 1.1MM; MFG_NAME01: NEXPERIA; ROHS: Yes; VOLTAGE: 1.2- 5.5V
U15 = 74AUP1G07GW: IC BUF NON-INV SGL 1.65-5.5V AEC-Q100 TSSOP5; 3D_Mechanical_Footprint_File: http://fcl.am.freescale.net/ALLEGRO/step/sc70-5.STEP; AGILE_PN: 312-82179; CAD_APPROVED: Yes; HEIGHT: 1.1MM; MFG_NAME01: NEXPERIA; MFG_PN01: 74LVC1G07GW-Q100H; ROHS: Yes; Temp Range: -40 to +125C; VOLTAGE: 1.65-5.5V
C107 = CAP_NP: CAP CER 10UF 35V 20% X5R 0603; AGILE_PN: 150-79911; CAD_APPROVED: Yes; HEIGHT: 1MM; MFG_NAME01: MURATA; MFG_PN01: GRM188R6YA106MA73D; ROHS: Yes; Rated Voltage: 35V; Temp Range: -55C to +85C; Tolerance: 10%; VOLTAGE: 35V
C109 = CAP_POL: CAP TANT 10UF 16V 10% -- 3216-18; 3D_Mechanical_Footprint_File: http://fcl.am.freescale.net/ALLEGRO/step/cc3216.step; AGILE_PN: 150-75055; CAD_APPROVED: YES; HEIGHT: 1.8MM; MFG_NAME01: AVX; MFG_PN01: TAJA106K016R; Package Size: 3216-18; Package Type: 7" TAPE/REEL; ROHS: Yes; Rated Voltage: 16V; Tolerance: 10%; VOLTAGE: 16V
C110 = CAP_NP: CAP CER 4700PF 50V 10% X7R 0603; AGILE_PN: 150-30078; CAD_APPROVED: Yes; FPLIST: CC0603_OV,CC0603,0603_CC; HEIGHT: 0.90MM; MFG_NAME01: YAGEO AMERICA; MFG_PN01: CC0603KRX7R9BB472; ROHS: Yes; Rated Voltage: 50V; Temp Range: -55C to +125C; Tolerance: 10%; VOLTAGE: 50V
D8 = DIODE: DIODE RECT SW 1A 400V AEC-Q101 SOD123W; AGILE_PN: 480-79648; CAD_APPROVED: Yes; HEIGHT: 1.1MM; MFG_NAME01: NEXPERIA; MFG_PN01: PNS40010ER,115; ROHS: Yes
J9 = DC_POWER_JACK_SHD: CON 3 PWR JACK RA TH 295H -- NI 98L; 3D_Mechanical_Footprint_File: http://fcl.am.freescale.net/ALLEGRO/step/con3_pwr_jack_th_pj051a.step; AGILE_PN: 210-79945; CAD_APPROVED: Yes; HEIGHT: 7.5MM; MFG_NAME01: CUI INC; MFG_PN01: PJ-051A; ROHS: Yes
J10 = CONN_HDR_4X1: HDR 1X4 TH RA 100MIL SP 268H AU 124L; 3D_Mechanical_Footprint_File: http://fcl.am.freescale.net/ALLEGRO/step/con_hdr_4m_100_th_ra.STEP; AGILE_PN: 210-79929; CAD_APPROVED: Yes; HEIGHT: 6.81MM; MFG_NAME01: MOLEX; MFG_PN01: 0022122041; ROHS: Yes
JP13 = CONN_HDR_3X1: HDR 1X3 TH 100MIL SP 340H AU 118L; 3D_Mechanical_Footprint_File: http://fcl.am.freescale.net/ALLEGRO/step/hdr103.STEP; AGILE_PN: 210-30160; CAD_APPROVED: Yes; FPLIST: CONN_HDR_3X1,HDR103; HEIGHT: 8.79MM; Jumper (Default): 1-2; MFG_NAME01: HARWIN INC; MFG_PN01: M20-9990345; ROHS: Yes
JP14 = CONN_HDR_3X1: HDR 1X3 TH 100MIL SP 340H AU 118L; 3D_Mechanical_Footprint_File: http://fcl.am.freescale.net/ALLEGRO/step/hdr103.STEP; AGILE_PN: 210-30160; CAD_APPROVED: Yes; FPLIST: CONN_HDR_3X1,HDR103; HEIGHT: 8.79MM; Jumper (Dafault): 1-2; MFG_NAME01: HARWIN INC; MFG_PN01: M20-9990345; ROHS: Yes
Q3 = MOSFET_N: TRAN NMOS 60V 360MA AEC-Q101 TO-236AB; AGILE_PN: 480-79842; CAD_APPROVED: Yes; HEIGHT: 1.1MM; MFG_NAME01: NEXPERIA; MFG_PN01: BSS138P,215; ROHS: Yes; Temp Range: -65°C ~ 150°C; Temp_Range: -65°C ~ 150°C; VOLTAGE: 60V
R45 R99 = RES: RES MF 60.4 OHM 1/8W 1% 0805; AGILE_PN: 470-77684; CAD_APPROVED: Yes; FPLIST: RC0805_OV,RC0805,0805_CC; HEIGHT: 0.6MM; MFG_NAME01: YAGEO AMERICA; MFG_PN01: 232273466049L; ROHS: Yes; Tolerance: 1%; VOLTAGE: 150V
R86 = RES: RES MF 10K 1/16W 1% 0402; AGILE_PN: 470-80452; CAD_APPROVED: Yes; FPLIST: RC0402_25,RC0402_HD,0402_CC,RC0402_X2; HEIGHT: 0.40 MM; MFG_NAME01: NIC COMPONENTS CORP; MFG_PN01: NRCL04F1002TRF; ROHS: Yes; TOL: 5%; Tolerance: 1%
R97 = RES: RES MF 4.7K 1/16W 5% 0402; AGILE_PN: 470-75626; CAD_APPROVED: Yes; FPLIST: RC0402_25,RC0402_HD,0402_CC; HEIGHT: 0.41mm; MFG_NAME01: BOURNS; MFG_PN01: CR0402-JW-472GLF; ROHS: Yes; TOL: 1%; Tolerance: 5%
R98 R100 = RES: RES MF ZERO OHM 1/16W 5% 0402; AGILE_PN: 470-75394; CAD_APPROVED: Yes; FPLIST: RC0603_OV,RC0603,R603-X2,0603_CC; HEIGHT: 0.45 MM; MFG_NAME01: BOURNS; MFG_PN01: CR0402-J/-000GLF; ROHS: Yes; Tolerance: 5%; VOLTAGE: 1/16W
U16 = 74AVC4TD245BQ_DHVQFN16: IC DUAL SUPPLY XCVR XLTR 4BIT 0-3.6V DHVQFN16; 3D_Mechanical_Footprint_File: http://fcl.am.freescale.net/ALLEGRO/step/dhvqfn16_0p5_3p6x2p6.STEP; AGILE_PN: 312-81329; CAD_APPROVED: Yes; HEIGHT: 1MM; MFG_NAME01: NEXPERIA; MFG_PN01: 74AVC4TD245BQ,115; ROHS: Yes
U17 U20 = 74LVCH1T45_6P: IC XCVR 1BIT 3-STATE DUAL 1.2-5.5V XSON6; AGILE_PN: 312-80758; CAD_APPROVED: Yes; HEIGHT: 0.5MM; MFG_NAME01: NEXPERIA; MFG_PN01: 74LVCH1T45GM,132; ROHS: Yes; VOLTAGE: 1.2-5.5V
U18 = LD1117AS18: IC VREG LDO 5V 1A 20V SOT223; AGILE_PN: 315-79374; CAD_APPROVED: Yes; HEIGHT: 1.8MM; MFG_NAME01: ON SEMICONDUCTOR; ROHS: Yes; VOLTAGE: 5V
U19 = TJA1057GT3_8P: IC XCVR CAN 4.75-5.25V/2.95-5.25V AEC-Q100 SO8; 3D_Mechanical_Footprint_File: http://fcl.am.freescale.net/ALLEGRO/step/so8_1p27_4x5.step; AGILE_PN: 312-81479; CAD_APPROVED: Yes; HEIGHT: 1.75MM; MFG_NAME01: NXP SEMICONDUCTORS; ROHS: Yes; VOLTAGE: 4.75-5.25V/2.95-5.25V

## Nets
GND: C51.2 C52.2 C53.2 C54.2 C55.2 C56.2 C57.2 C58.2 C59.2 C60.2 C61.2 C62.2 C63.2 C64.2 C65.2 C66.2 C67.2 C68.2 C69.2 C70.2 C71.2 C72.2 C73.2 C74.2 C75.2 C76.2 C77.2 C78.2 C79.2 C80.2 C81.2 C82.2 C83.2 C84.2 C85.2 C86.2 C87.2 C88.2 C89.2 C90.2 C91.2 C92.2 C93.2 C94.2 C95.2 C103.2 C104.2 C105.2 C106.2 C107.2 C108.2 C109.2 C110.1 C111.2 C112.2 C113.2 D13.A D14.A D15.2(A) J3.5(GND) J4.3(A2) J4.5(A3) J4.9(A5) J5.3(A2) J5.5(A3) J9.2 J9.3 J9.SH1(SHIELD1) J9.SH2(SHIELD2) J10.4 JP12.1 JP21.1 JP22.1 L9.2 Q3.2(SOURCE) R38.1 R41.2 R44.2 R53.2 R66.2 R70.2 R71.2 R74.2 R77.2 R79.2 R80.2 R96.2 R104.2 R105.2 R106.2 SW4.G1(GND1) SW4.G2(GND2) SW4.G3(GND3) SW4.G4(GND4) U6.18(VREFN) U6.19(VSSA) U6.33(USB1_VSS_2) U6.37(USB1_VSS_1) U6.46(VSS_DCDC1) U6.47(VSS_DCDC2) U6.52(XTAL32K_P) U6.99(USB0_VSS) U6.101(EPAD) U7.2(ANODE) U7.3(ANODE/NC) U8.2(VSS) U9.7(GND) U10.4(GND) U11.6(GND) U12.2(GND) U13.2(GND) U14.2(GND) U15.3(GND) U16.2(DIR1) U16.5(A3) U16.6(A4) U16.8(GND1) U16.17(NC/GND2) U17.2(GND) U18.1(GND) U19.2(GND) U19.8(S) U20.2(GND) U20.5(DIR) ; also on sheet 3 4 5
P5V: D4.C R97.1 ; also on sheet 4
P5V_CAN: C103.1 C105.1 C106.1 C109.1 C111.1 U17.1(VCCA) U18.2(VOUT) U18.4(TAB) U19.3(VCC) U19.5(VIO) U20.1(VCCA) ; also on sheet 4
P12V: D8.A(ANODE) J9.1 J10.3
P12V_VBAT: C107.1 C108.1 D8.C(CATHODE) U18.3(VIN)
VBAT_DCDC/VBAT_PMU: C68.1 C69.1 C72.1 L7.2 U6.49(VBAT_DCDC_1) U6.50(VBAT_DCDC_2) U6.51(VBAT__PMU)
VBUS_USB: C81.1 J3.1(VBUS) L8.1 U9.6(VBUS)
VCC_IF_LINK: C85.1 C88.1 C90.1 C91.1 C93.1 J5.1(A1) JP18.2 R43.1 R68.1 R72.1 R75.1 R76.1 SW4.1(S1) U10.8(VCCB) U12.6(VCCB) U13.6(VCCB) U14.6(VCCB) U15.5(VCC)
VCC_TGMCU: C84.1 C94.1 D12.A JP18.1 R67.2 R86.1 R101.1 SH15.2 U11.14(VCC) U16.1(VCCA) U16.7(DIR4) U16.10(DIR3) U16.15(DIR2)
BOOT_CFG: C113.1 JP16.2 SW4.2(S2)
CAN_DIR: R97.2 U17.5(DIR)
CAN_HI: J10.1 R99.2 U19.7(CANH)
CAN_LO: J10.2 R45.1 U19.6(CANL)
CAN_RX: U17.3(A) U19.4(RXD)
CAN_TX: U19.1(TXD) U20.3(A)
DBGIF_DETECT: R81.1 U6.78(PIO0_22)
DBGIF_ISP0_CTRL: U6.72(PIO0_14) U15.2(A)
DBGIF_RESET: U6.90(PIO0_19) U14.3(A)
DBGIF_RESET_TXEN: R80.1 U6.71(PIO0_13) U14.5(DIR)
DBGIF_TCK_SWCLK: U6.54(PIO0_0/ACMP0_A) U10.2(1A)
DBGIF_TDI: U6.7(PIO0_1) U10.3(2A)
DBGIF_TDO_SWO: U6.83(PIO0_3/TCK) U12.3(A)
DBGIF_TMS_SWDIO: U6.81(PIO0_2/TRST) U13.3(A)
DBGIF_TMS_SWDIO_TXEN: R74.1 U6.66(PIO0_28/WAKEUP) U13.5(DIR)
DBGIF_VREF: C82.1 R43.2 R44.1 U6.23(PIO0_31/ADC0_3)
FL_USB1_DM: R39.2 U6.35(USB1_DM)
FL_USB1_DP: R40.2 U6.34(USB1_DP)
FL_USB_5V0: C75.1 C76.1 D4.A L8.2 R37.1 U8.1(CE) U8.4(VIN)
HW_VER_1: R102.1 U6.73(PIO1_28)
HW_VER_2: R104.1 U6.65(PIO1_30/WAKEUP)
HW_VER_3: R105.1 U6.1(PIO1_4)
HW_VER_4: R106.1 U6.31(PIO1_5)
HW_VER_6: JP21.2 Q3.1(GATE) U6.56(PIO0_18/ACMP0_C)
HW_VER_7: JP22.2 U6.27(PIO0) U10.5(DIR)
HW_VER_8: R96.1 U6.55(PIO0_9/ACMP0_B)
IF_DETECT: D14.C J5.9(A5) R77.1 R81.2
IF_ISPEN: D13.C J5.7(A4) R83.2
IF_TCK_SWDCLK: D15.5(K4) J5.4(B2) R63.2 R79.1 U11.3(2Y1)
IF_TDI: D15.3(K2) J5.8(B4) R64.2
IF_TDO_SWO: D15.4(K3) J5.6(B3) R69.2 U11.11(4Y1)
IF_TMS_SWDIO: D15.6(K5) J5.2(B1) R73.2 R75.2 U11.15(1Y1)
IF_TRGRST_SWDRST: D15.1(K1) J5.10(B5) R78.2 U11.7(3Y1)
MCU_LINK_3V3: C51.1 C52.1 C54.1 C55.1 C56.1 C57.1 C58.1 C59.1 C60.1 C61.1 C62.1 C79.1 C80.1 L4.2 U6.15(VDD_1) U6.25(VDD_2) U6.38(USB1_3V3) U6.44(VDD_3) U6.63(VDD_4) U6.69(VDD_5) U6.75(VDD_6) U6.84(VDD_7) U6.95(VDD_8) U6.96(USB0_3V3) U6.100(VDD_9)
MCU_LINK_N_16MHz: C78.1 U6.28(XTAL32M_N) Y4.1
MCU_LINK_P_16MHz: C77.1 U6.29(XTAL32M_P) Y4.2
MCU_LINK_RST: J4.10(B5) U6.32(RESETN)
MCU_LNK_RX: U6.70(PIO0_24) U16.13(B2)
MCU_LNK_TX: U6.79(PIO0_25) U16.14(B1)
MCULINK_VDDA: C63.1 C64.1 L5.2 R33.1 U6.16(VDDA)
MLINK_3V3: C53.1 C83.1 C86.1 C87.1 C89.1 C92.1 C95.1 J4.1(A1) L4.1 L5.1 L7.1 R34.2 R46.1 R47.1 R48.1 R50.1 R102.2 U10.1(VCCA) U12.1(VCCA) U13.1(VCCA) U14.1(VCCA) U16.16(VCCB)
MLINK_FB: C65.1 C66.1 C67.1 L6.2 U6.39(VDD_PMU) U6.45(FB)
MLINK_LX: L6.1 U6.48(LX)
PIO0_5-ISP_EN: J4.7(A4) R51.2
PIO0_5-ISP_EN-LED_SWD_ACT: D7.C(CATHODE) JP12.2 R48.2 R51.1 U6.88(PIO0_5/TDI)
PIO0_10-SWO: J4.6(B3) R46.2 U6.21(PIO0_10/ADC0_1)
PIO0_11-SWDCLK: J4.4(B2) R53.1 U6.13(PIO0_11/ADC0_9)
PIO0_12-SWDIO: J4.2(B1) R47.2 U6.12(PIO0_12/ADC0_10)
PTA0/SWD_DIO: U11.16(1Z) ; also on sheet 3
PTA1/SWD_CLK: R66.1 U11.4(2Z) ; also on sheet 3
PTA4/SWO/BOOT_CFG: JP16.1 U11.12(4Z) ; also on sheet 3
PTA16: JP13.3 ; also on sheet 3 4
PTA17: JP14.3 ; also on sheet 3 4
PTC2: JP13.1 ; also on sheet 3
PTC3: JP14.1 ; also on sheet 3
PTC4: R100.2 ; also on sheet 3
PTC5: R98.2 ; also on sheet 3
RST_TGTMCU_b: JP25.2 ; also on sheet 3 4 5
RST_U11: JP25.1 U11.8(3Z)
USB1_VBUS: R37.2 R41.1 U6.36(USB1_VBUS)
V_BRD: C104.1 C112.1 SH15.1 U17.6(VCCB) U20.6(VCCB) ; also on sheet 3 4 5
VOUT_MLINK: C73.1 C74.1 R34.1 U8.5(VOUT)
VREF_MCULINK: C70.1 C71.1 R33.2 R42.2 U6.17(VREFP) U7.1(CATHODE)
N22669333: R63.1 U10.7(1B)
N22669352: R64.1 U10.6(2B)
N22669391: R65.1 U11.1(1Y0)
N22669418: JP17.1 R65.2 R67.1 U11.2(S) U11.5(2Y0) U11.9(3Y0)
N22669601: R70.1 U12.5(DIR)
N22669605: R68.2 R69.1 U12.4(B)
N22669808: R72.2 R73.1 U13.4(B)
N22669908: D12.C JP18.3
N22670160: R76.2 R78.1 U14.4(B)
N22670341: R83.1 U15.4(Y)
N22888978: JP17.2 R71.1
N22954457: R84.1 U16.3(A1)
N22954468: R85.1 R101.2 U16.4(A2)
N22954480: Q3.3(DRAIN) R86.2 U16.9(~{OE})
N23489789: J3.6(SHELL1) J3.7(SHELL2) J3.8(SHELL3) J3.9(SHELL4) L9.1
N23489809: J3.4(ID) TP21.1(TP) U9.3(USB_ID)
N23489851: J3.2(D-) R39.1 U9.1(DM)
N23489871: J3.3(D+) R40.1 U9.2(DP)
N23559922: R38.2 R42.1 U6.58(PIO1_19/ACMPVREF)
N23788677: R98.1 U17.4(B)
N23788861: C110.2 R45.2 R99.1
N23789034: R100.1 U20.4(B)
N23802482: D7.A(ANODE) R50.2
N23938720: JP13.2 R84.2
N23938761: JP14.2 R85.2

Not connected (* = marked no-connect by the designer): J4 8(B4)*; U6 2(PIO1_13)* 3(PIO1_24)* 4(PIO1_20)* 5(PIO1_6)* 6(PIO0_7)* 8(PIO0_17)* 9(PIO1_7)* 10(PIO1_9/ADC0_12)* 11(PIO1_0/ADC0)* 14(PIO0_16/ADC0_8)* 20(PIO0_23/ADC0_0)* 22(PIO0_15/ADC0_2)* 24(PIO1_8/ADC0_4)* 26(PIO0_8)* 30(PIO1_21)* 40(PIO1_10)* 41(PIO1_22)* 42(PIO1_23)* 43(PIO1_17)* 53(XTAL32K_N)* 57(PIO1_14/ACMP0_D)* 59(PIO1_1/WAKEUP)* 60(PIO0_26)* 61(PIO1_2)* 62(PIO1_3)* 64(PIO1_18/WAKUP)* 67(PIO1_12)* 68(PIO1_26)* 74(PIO0_20)* 76(PIO0_21)* 77(PIO1_25)* 80(PIO1_29)* 82(PIO1_15)* 85(PIO1_27)* 86(PIO0_4/TMS)* 87(PIO1_16)* 89(PIO0_6/TDO)* 91(PIO1_31)* 92(PIO0_29)* 93(PIO1_11)* 94(PIO0_30)* 97(USB0_DP)* 98(USB0_DM)*; U8 3(NC)*; U9 4(NC1)* 5(NC2)*; U11 10(NC)* 13(4Y0)*; U15 1(NC)*; U16 11(B4)* 12(B3)*

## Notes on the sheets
sheet 6
- MCU LINK
- 3V3 MCULINK Regulator
- Place C65 & C66
  close to Pin 29
- Place C97, C98 & C101
  close to Pin 49, 50, 51
- MCULINK LEDs
- SWD Activity
- MCULink USB
- HW VER
- MICRO B
- MCULINK SWD
  connector
- PU
- F
- PU
- Open  : Boot from Internal Flash
  Closed: Enable ISP mode (USB1)
sheet 7
- MCU LINK
- Target MCU
- Default  3.3V
- Debug Interface
- SWD_DIO
- SWD_CLK
- DIR#  L: B to A, H: A to B
- MCU RST
- SWO/BOOT_CONF
- S#  L:Z-Y0, H:Z-Y1
- DIR#  L: B to A, H: A to B
- Link2 probe connected to:
- On-board Target
  Off-board Target
- Open (default)
  Shorted
- 10pin JTAG/SWD
- DIR#  L: B to A, H: A to B
- Buffer Power Select:
- On-board Target
  Off-board Target
- 1 - 2 (default)
  2 - 3
- DIR#  L: B to A, H: A to B
- BOOT CONFIG
sheet 8
- MCU LINK
- Voltage Translation
  Buffers
- Note: Pullup (R101)prevents random output
  on terminal before UART is configured
- Target MCU
- LPUART1_RX
- Target Side
- Debugger Side
- TGTMCU_RX
- LPUART0_RX
- TGTMCU_TX
- LPUART1_TX
- LPUART0_TX
- DIR#  L: B to A
  H: A to B
- CAN SUPPORT
- CAN Power
- External 12V
- CAN0_RX
- CAN0_TX
